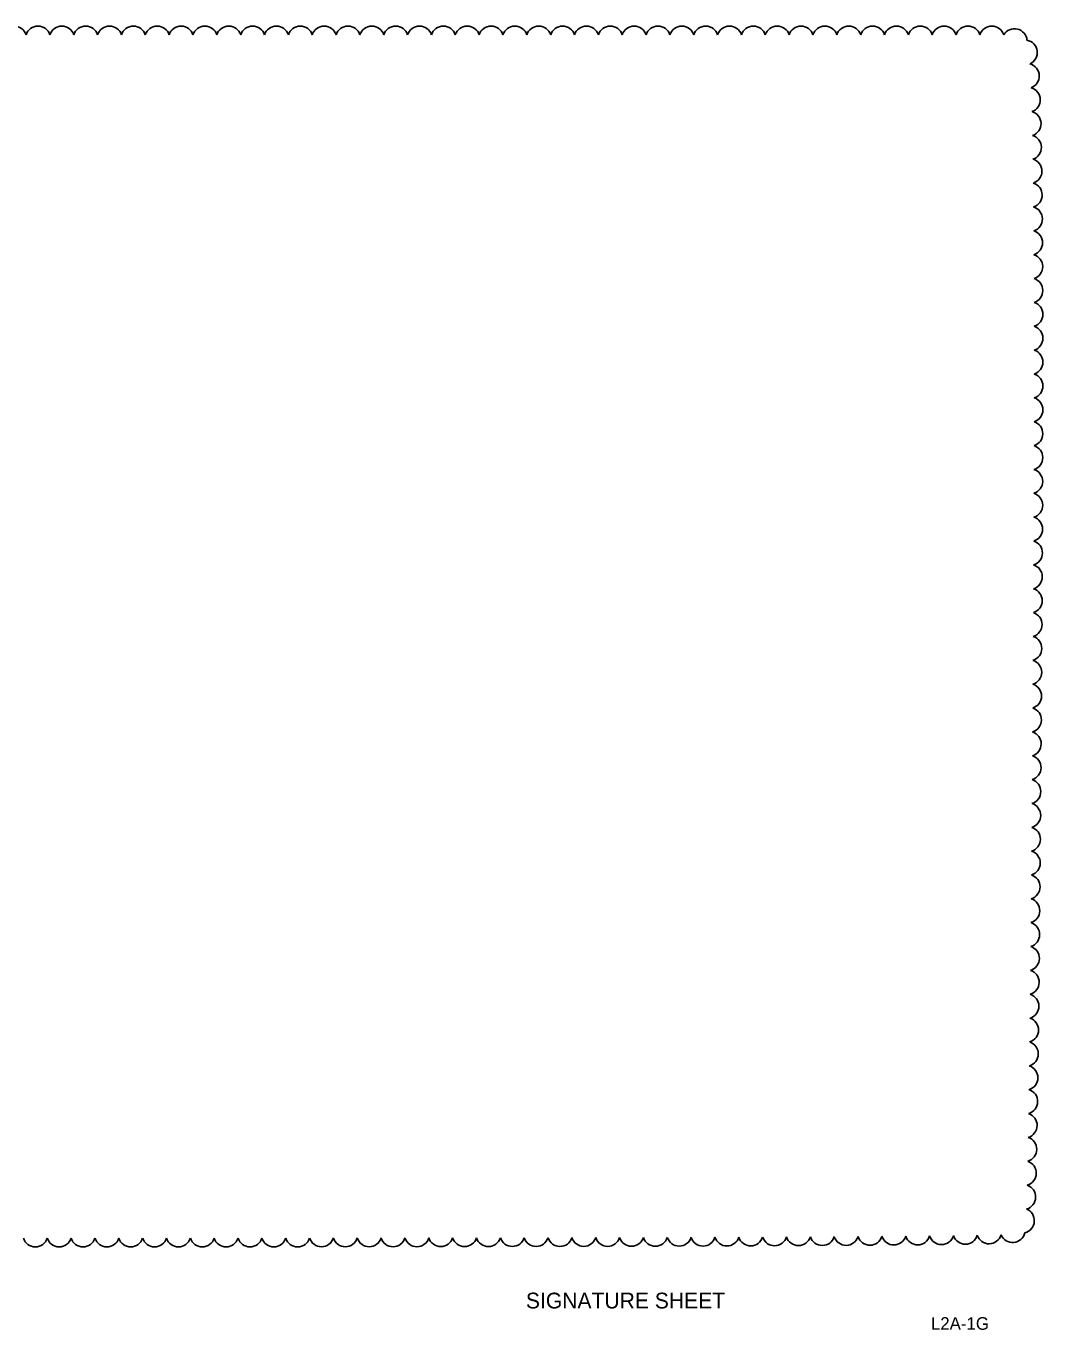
# Model space of a CAD drawing. Extents: x -811 to -790, y -2284 to -2178.
# Drawn here: x -803.16 to -795.1, y -2284.04 to -2273.71 of the extents above; entities that cross this region are included whole.
import ezdxf

# ---------------------------------------------------------------- set-up
doc = ezdxf.new("R2010")
doc.units = 0
for name, color, linetype in [('PlotBorder_dp', 7, 'Continuous'), ('ScratchEle_dp', 7, 'Continuous'), ('SheetLines_dp', 7, 'Continuous')]:
    doc.layers.add(name, color=color, linetype=linetype)

msp = doc.modelspace()

# ---------------------------------------------------------------- linework, layer by layer
at = {"layer": 'ScratchEle_dp'}
for centre, radius, start, end in [((-803.255, -2273.807), 0.0991, 17.5008, 162.5008), ((-803.066, -2273.807), 0.0991, 17.5, 162.5), ((-802.877, -2273.807), 0.0991, 17.5, 162.5), ((-802.688, -2273.807), 0.0991, 17.5, 162.5), ((-802.499, -2273.807), 0.0991, 17.5, 162.5), ((-802.31, -2273.807), 0.0991, 17.5, 162.5), ((-802.121, -2273.807), 0.0991, 17.5, 162.5), ((-801.932, -2273.807), 0.0991, 17.5, 162.5), ((-801.743, -2273.807), 0.0991, 17.5, 162.5), ((-801.554, -2273.807), 0.0991, 17.5, 162.5), ((-801.365, -2273.807), 0.0991, 17.5, 162.5), ((-801.176, -2273.807), 0.0991, 17.5, 162.5), ((-800.987, -2273.807), 0.0991, 17.5, 162.5), ((-800.798, -2273.807), 0.0991, 17.5, 162.5), ((-800.609, -2273.807), 0.0991, 17.5, 162.5), ((-800.42, -2273.807), 0.0991, 17.5, 162.5), ((-800.231, -2273.807), 0.0991, 17.5, 162.5), ((-800.042, -2273.807), 0.0991, 17.5, 162.5), ((-799.853, -2273.807), 0.0991, 17.5, 162.5), ((-799.664, -2273.807), 0.0991, 17.5, 162.5), ((-799.475, -2273.807), 0.0991, 17.5, 162.5), ((-799.286, -2273.807), 0.0991, 17.5, 162.5), ((-799.097, -2273.807), 0.0991, 17.5, 162.5), ((-798.908, -2273.807), 0.0991, 17.5, 162.5), ((-798.719, -2273.807), 0.0991, 17.5, 162.5), ((-798.53, -2273.807), 0.0991, 17.5, 162.5), ((-798.341, -2273.807), 0.0991, 17.5, 162.5), ((-798.152, -2273.807), 0.0991, 17.5, 162.5), ((-797.963, -2273.807), 0.0991, 17.5, 162.5), ((-797.774, -2273.807), 0.0991, 17.5, 162.5), ((-797.585, -2273.807), 0.0991, 17.5, 162.5), ((-797.396, -2273.807), 0.0991, 17.5, 162.5), ((-797.207, -2273.807), 0.0991, 17.5, 162.5), ((-797.018, -2273.807), 0.0991, 17.5, 162.5), ((-796.829, -2273.807), 0.0991, 17.5, 162.5), ((-796.64, -2273.807), 0.0991, 17.5, 162.5), ((-796.451, -2273.807), 0.0991, 17.5, 162.5), ((-796.262, -2273.807), 0.0991, 17.5, 162.5), ((-796.073, -2273.807), 0.0991, 17.5, 162.5), ((-795.884, -2273.807), 0.0991, 17.5, 162.5), ((-795.695, -2273.807), 0.0991, 17.5, 162.5), ((-795.506, -2273.807), 0.0991, 17.5, 162.5), ((-795.326, -2273.828), 0.099, 4.4162, 149.4162), ((-795.245, -2273.918), 0.0992, 294.7802, 79.7802), ((-795.229, -2274.104), 0.0991, 290.3649, 75.3649), ((-795.221, -2274.292), 0.0991, 289.3839, 74.3839), ((-795.215, -2274.481), 0.0991, 288.8712, 73.8712), ((-795.212, -2274.669), 0.0991, 288.5423, 73.5423), ((-795.208, -2274.858), 0.0991, 288.3081, 73.3081), ((-795.206, -2275.047), 0.0991, 288.1304, 73.1304), ((-795.204, -2275.236), 0.0991, 287.9896, 72.9896), ((-795.203, -2275.425), 0.0991, 287.8744, 72.8744), ((-795.202, -2275.614), 0.0991, 287.778, 72.778), ((-795.201, -2275.803), 0.0991, 287.6956, 72.6956), ((-795.2, -2275.992), 0.0991, 287.6243, 72.6243), ((-795.2, -2276.181), 0.0991, 287.5617, 72.5617), ((-795.2, -2276.37), 0.0991, 287.5062, 72.5062), ((-795.2, -2276.559), 0.0991, 287.4565, 72.4565), ((-795.2, -2276.748), 0.0991, 287.4117, 72.4117), ((-795.201, -2276.937), 0.0991, 287.3711, 72.3711), ((-795.201, -2277.126), 0.0991, 287.3339, 72.3339), ((-795.202, -2277.315), 0.0991, 287.2999, 72.2999), ((-795.202, -2277.504), 0.0991, 287.2684, 72.2684), ((-795.203, -2277.693), 0.0991, 287.2394, 72.2394), ((-795.204, -2277.882), 0.0991, 287.2123, 72.2123), ((-795.205, -2278.071), 0.0991, 287.1871, 72.1871), ((-795.206, -2278.26), 0.0991, 287.1635, 72.1635), ((-795.207, -2278.449), 0.0991, 287.1414, 72.1414), ((-795.209, -2278.638), 0.0991, 287.126, 72.126), ((-795.21, -2278.827), 0.0991, 287.1162, 72.1162), ((-795.211, -2279.016), 0.0991, 287.1058, 72.1058), ((-795.212, -2279.205), 0.0991, 287.0946, 72.0946), ((-795.214, -2279.394), 0.0991, 287.0827, 72.0827), ((-795.215, -2279.583), 0.0991, 287.0698, 72.0698), ((-795.217, -2279.772), 0.0991, 287.0559, 72.0559), ((-795.218, -2279.961), 0.0991, 287.0408, 72.0408), ((-795.22, -2280.15), 0.0991, 287.0244, 72.0244), ((-795.221, -2280.338), 0.0991, 287.0064, 72.0064), ((-795.223, -2280.527), 0.0991, 286.9865, 71.9865), ((-795.225, -2280.716), 0.0991, 286.9645, 71.9645), ((-795.226, -2280.905), 0.0991, 286.94, 71.94), ((-795.228, -2281.094), 0.0991, 286.9123, 71.9123), ((-795.23, -2281.283), 0.0991, 286.8807, 71.8807), ((-795.232, -2281.472), 0.0991, 286.8443, 71.8443), ((-795.235, -2281.661), 0.0991, 286.8016, 71.8016), ((-795.237, -2281.85), 0.0991, 286.7507, 71.7507), ((-795.24, -2282.039), 0.0991, 286.6884, 71.6884), ((-795.242, -2282.228), 0.0991, 286.6098, 71.6098), ((-795.246, -2282.417), 0.0991, 286.5063, 71.5063), ((-795.249, -2282.606), 0.0991, 286.3609, 71.3609), ((-795.253, -2282.795), 0.0991, 286.1344, 71.1344), ((-795.258, -2282.984), 0.0991, 285.7012, 70.7012), ((-795.268, -2283.171), 0.099, 283.7418, 68.7418), ((-803.087, -2283.28), 0.0991, 197.4952, 342.4952), ((-802.898, -2283.28), 0.0991, 197.5007, 342.5007), ((-802.709, -2283.28), 0.0991, 197.5043, 342.5043), ((-802.52, -2283.28), 0.0991, 197.5079, 342.5079), ((-802.331, -2283.28), 0.0991, 197.5117, 342.5117), ((-802.142, -2283.28), 0.0991, 197.5156, 342.5156), ((-801.953, -2283.28), 0.0991, 197.5197, 342.5197), ((-801.764, -2283.28), 0.0991, 197.5239, 342.5239), ((-801.575, -2283.28), 0.0991, 197.5284, 342.5284), ((-801.386, -2283.28), 0.0991, 197.533, 342.533), ((-801.197, -2283.28), 0.0991, 197.5379, 342.5379), ((-801.008, -2283.28), 0.0991, 197.543, 342.543), ((-800.819, -2283.279), 0.0991, 197.5483, 342.5483), ((-800.63, -2283.279), 0.0991, 197.554, 342.554), ((-800.441, -2283.279), 0.0991, 197.5599, 342.5599), ((-800.252, -2283.279), 0.0991, 197.5662, 342.5662), ((-800.063, -2283.279), 0.0991, 197.5729, 342.5729), ((-799.874, -2283.278), 0.0991, 197.5799, 342.5799), ((-799.685, -2283.278), 0.0991, 197.5874, 342.5874), ((-799.496, -2283.278), 0.0991, 197.5954, 342.5954), ((-799.307, -2283.277), 0.0991, 197.604, 342.604), ((-799.118, -2283.277), 0.0991, 197.6131, 342.6131), ((-798.929, -2283.277), 0.0991, 197.623, 342.623), ((-798.74, -2283.276), 0.0991, 197.6337, 342.6337), ((-798.551, -2283.276), 0.0991, 197.6452, 342.6452), ((-798.362, -2283.275), 0.0991, 197.6578, 342.6578), ((-798.173, -2283.275), 0.0991, 197.6716, 342.6716), ((-797.984, -2283.274), 0.0991, 197.6868, 342.6868), ((-797.795, -2283.274), 0.0991, 197.7037, 342.7037), ((-797.606, -2283.273), 0.0991, 197.7225, 342.7225), ((-797.417, -2283.272), 0.0991, 197.7438, 342.7438), ((-797.228, -2283.271), 0.0991, 197.768, 342.768), ((-797.039, -2283.27), 0.0991, 197.796, 342.796), ((-796.85, -2283.269), 0.0991, 197.8288, 342.8288), ((-796.661, -2283.268), 0.0991, 197.8681, 342.8681), ((-796.472, -2283.267), 0.0991, 197.9161, 342.9161), ((-796.283, -2283.265), 0.0991, 197.9767, 342.9767), ((-796.094, -2283.264), 0.0991, 198.0568, 343.0568), ((-795.905, -2283.262), 0.0991, 198.1697, 343.1697), ((-795.716, -2283.259), 0.0991, 198.3466, 343.3466), ((-795.528, -2283.256), 0.0991, 198.6898, 343.6898), ((-795.341, -2283.246), 0.0992, 202.4244, 347.4244)]:
    msp.add_arc(centre, radius, start, end, dxfattribs=at)

# ---------------------------------------------------------------- texts
at = {"layer": 'PlotBorder_dp'}
msp.add_text('       SIGNATURE SHEET         ', height=0.125, dxfattribs=at).set_placement((-799.524, -2283.867))
at = {"layer": 'SheetLines_dp'}
msp.add_text('L2A-1G', height=0.1, dxfattribs=at).set_placement((-795.989, -2284.036))

doc.saveas('drawing.dxf')
